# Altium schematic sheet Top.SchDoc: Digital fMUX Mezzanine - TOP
size 817 x 513 mm; Engineer: M.Dobbs, McGill U.; Revision: 4; PageSetup: Record=PageOptions|CenterHorizontal=True|CenterVertical=True|PrintScale=0.52|XCorrection=1.00|YCorrection=1.00|PrintKind=0|BorderSize=5000000|LeftOffset=0|BottomOffset=0|Orientation=2|PaperLength=1000|PaperWidth=1000|Scale=100|PaperSource=15|PrintQuality=1200|MediaType=1|DitherType=10|PaperKind=11 x 17|PrintScaleMode=1
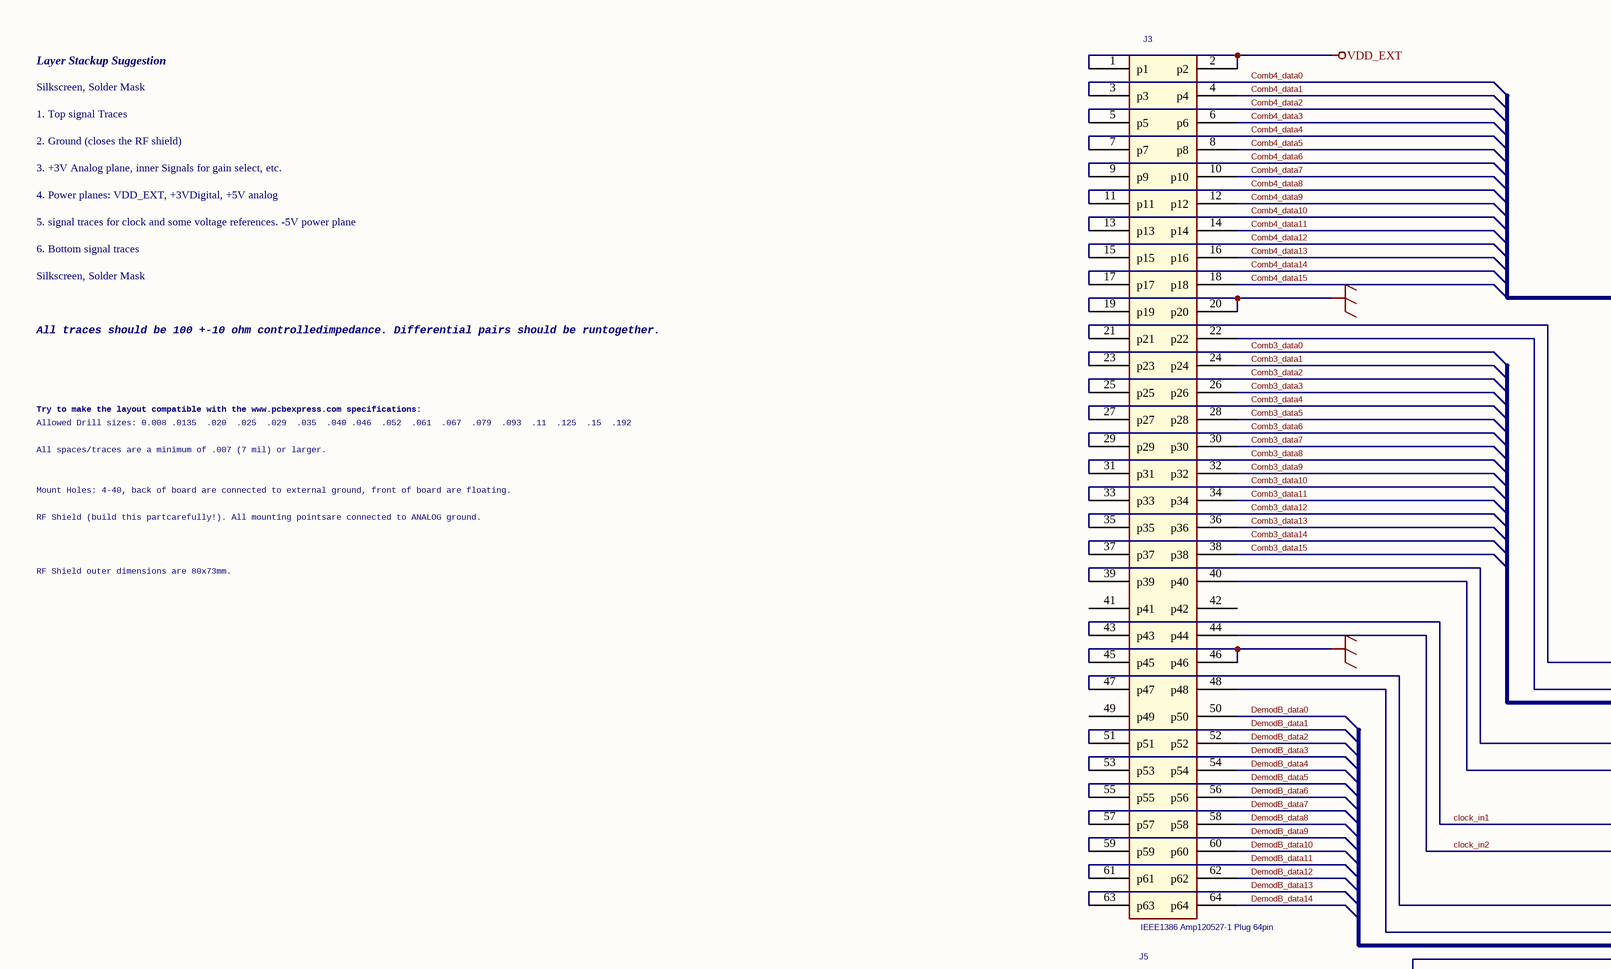
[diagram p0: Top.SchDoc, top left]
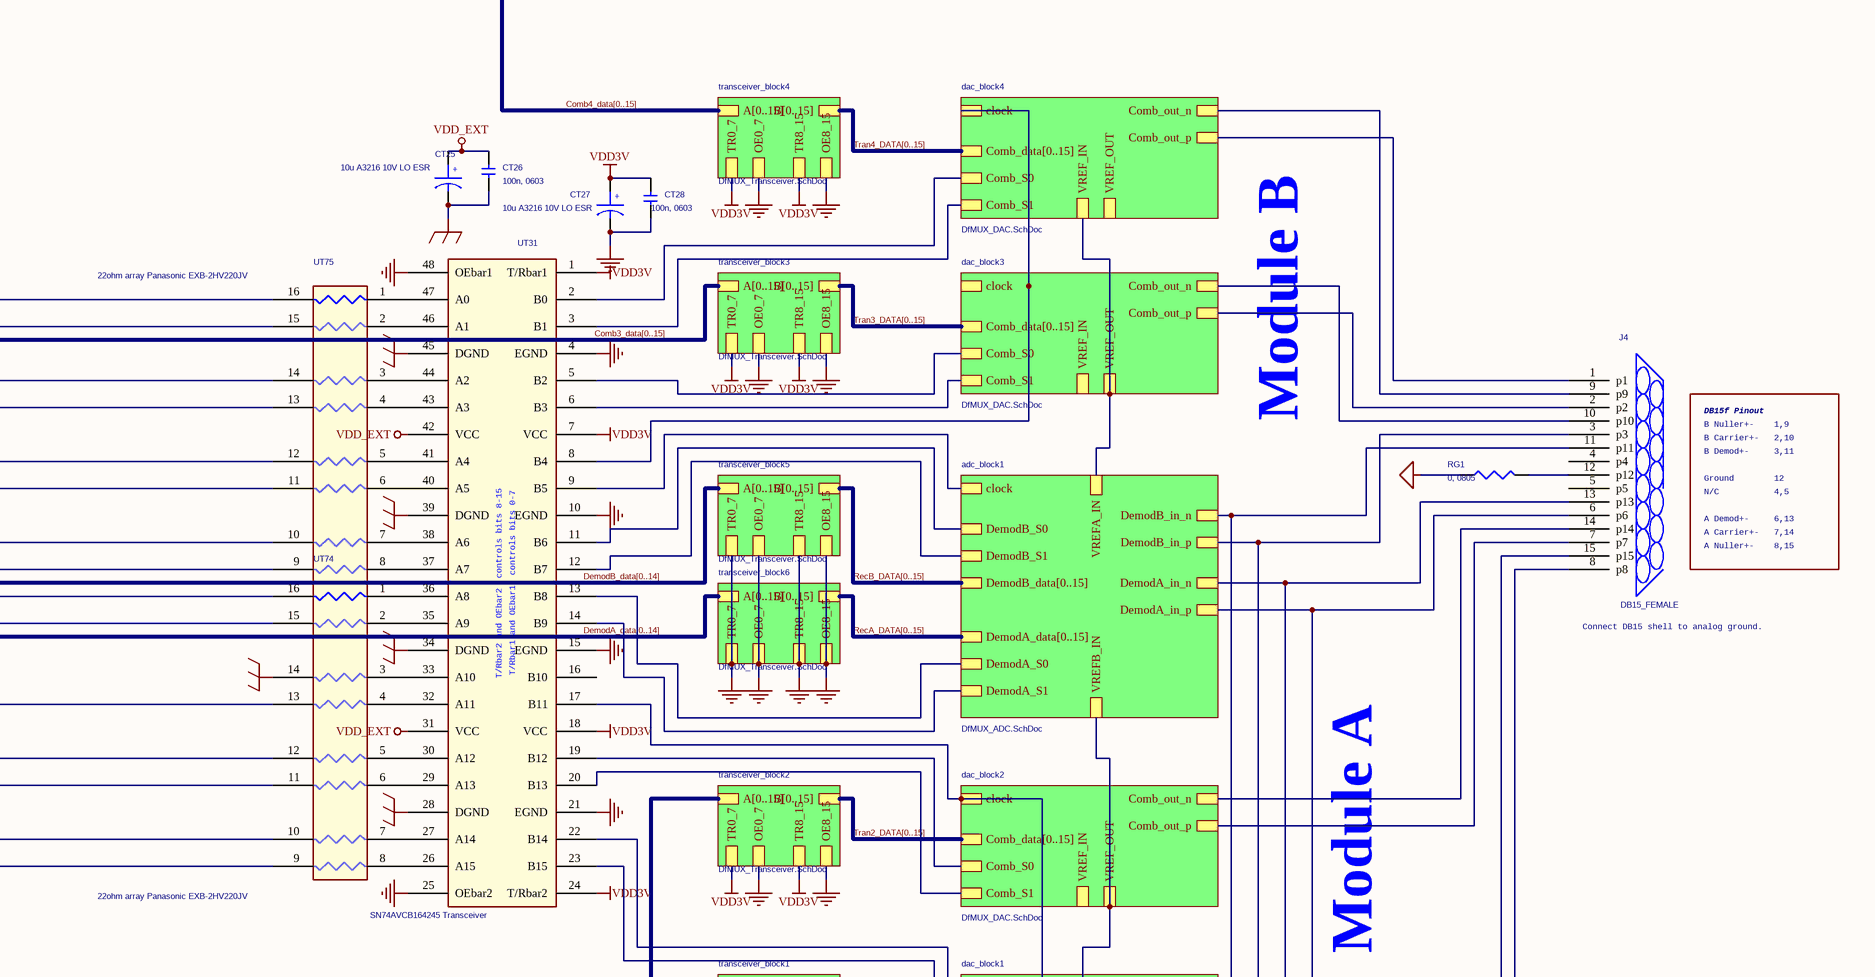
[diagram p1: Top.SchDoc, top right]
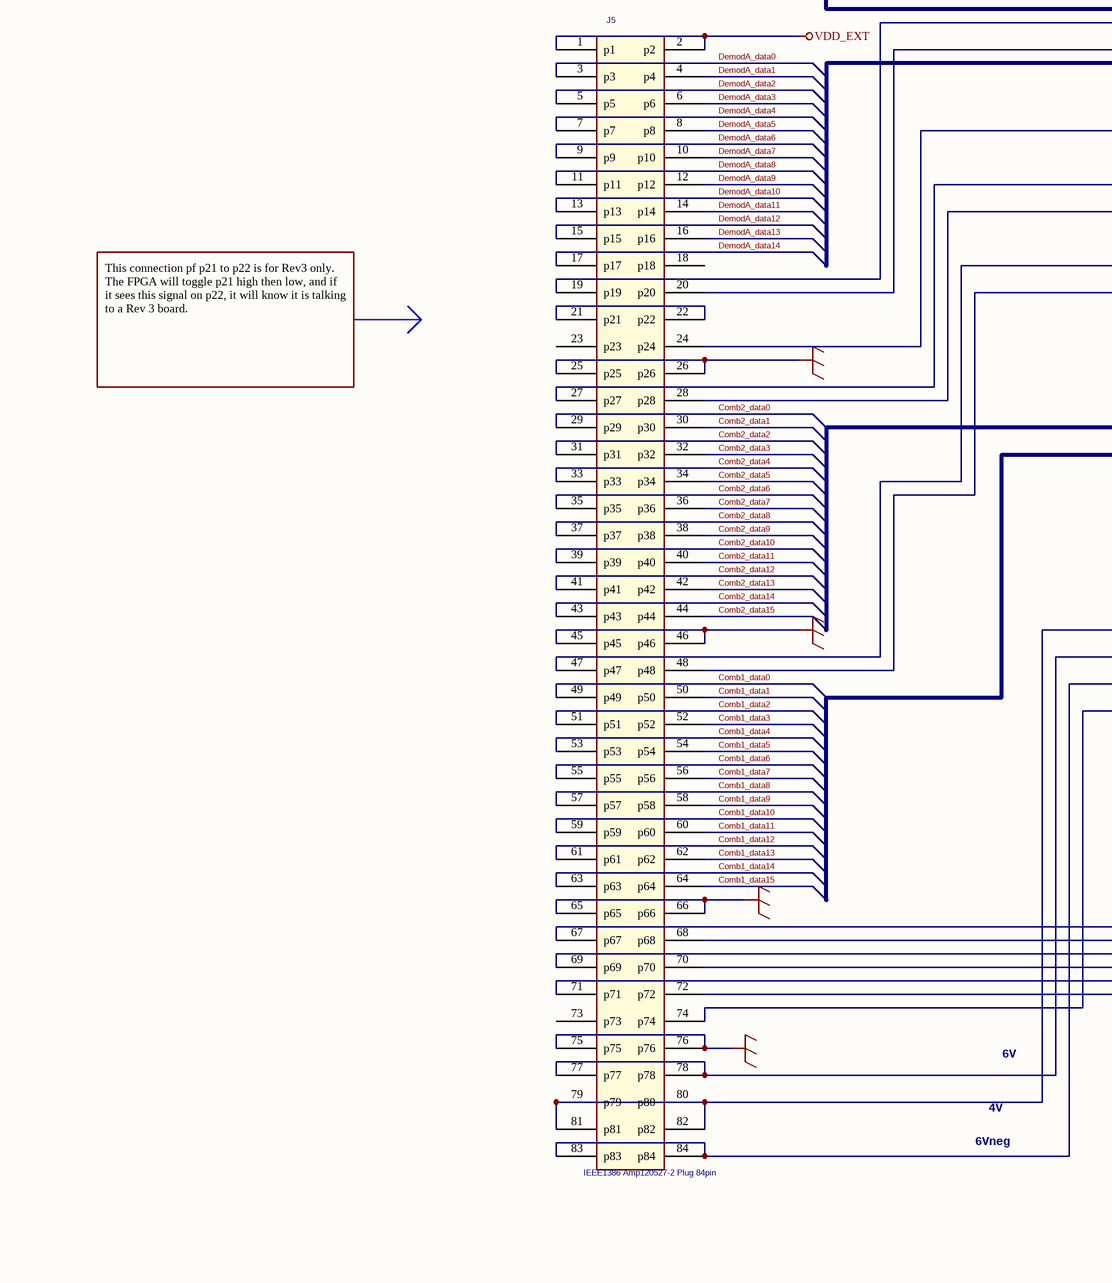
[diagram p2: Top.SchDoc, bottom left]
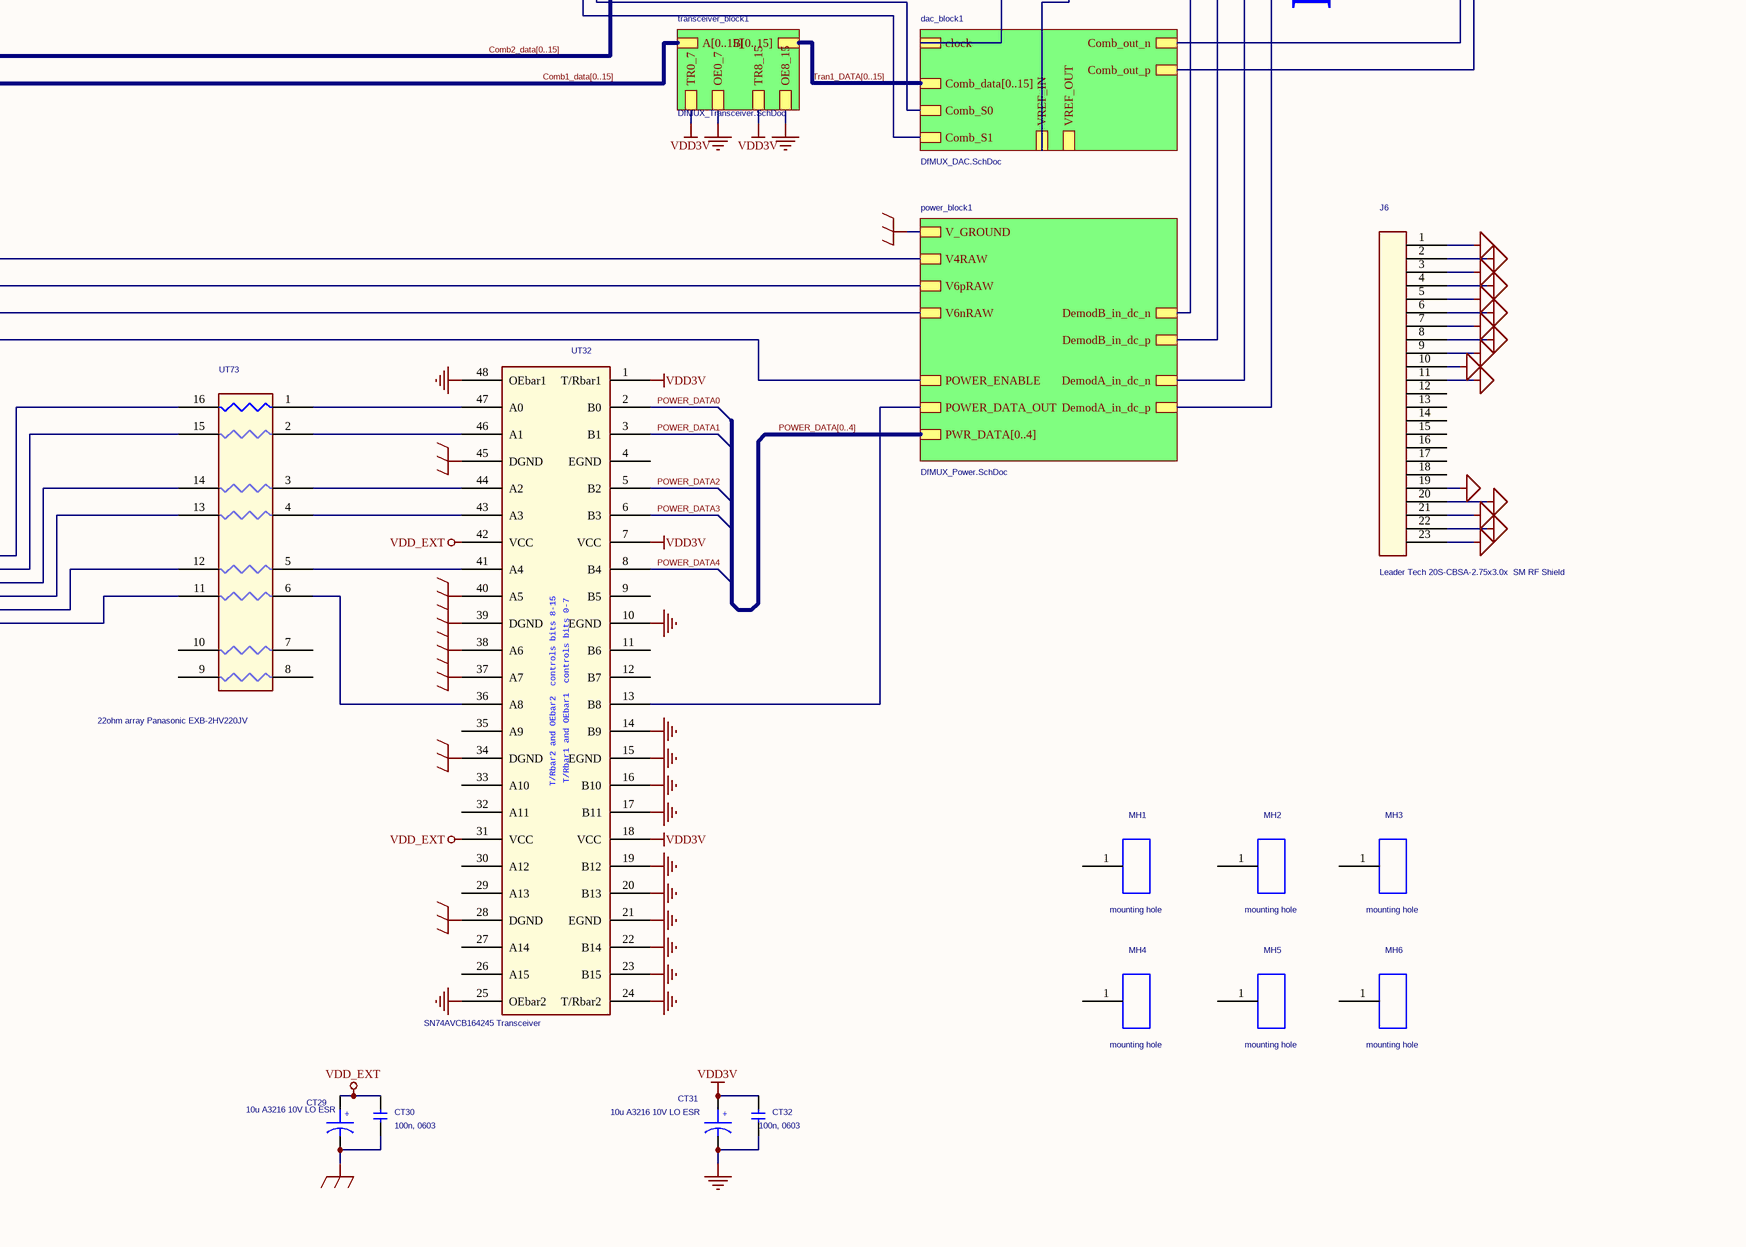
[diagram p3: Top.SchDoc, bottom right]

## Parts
CT25  10u A3216 10V LO ESR  [TANTA]
CT26  100n, 0603  [CK05]
CT27  10u A3216 10V LO ESR  [TANTA]
CT28  100n, 0603  [CK05]
CT29  10u A3216 10V LO ESR  [TANTA]
CT30  100n, 0603  [CK05]
CT31  10u A3216 10V LO ESR  [TANTA]
CT32  100n, 0603  [CK05]
J3  IEEE1386 Amp120527-1 Plug 64pin  [CON_AMP_1MM_64PINS]
J4  DB15_FEMALE  [DSUB/RS.318/TM/15]
J5  IEEE1386 Amp120527-2 Plug 84pin  [CON_AMP_1MM_84PINS]
J6  Leader Tech 20S-CBSA-2.75x3.0x  SM RF Shield  [SHIELD 2.75X3.00]
MH1  mounting hole  [MTHOLE.125]
MH2  mounting hole  [MTHOLE.125]
MH3  mounting hole  [MTHOLE.125]
MH4  mounting hole  [MTHOLE.125]
MH5  mounting hole  [MTHOLE.125]
MH6  mounting hole  [MTHOLE.125]
RG1  0, 0805
UT31  SN74AVCB164245 Transceiver  [TSSOP48]
UT32  SN74AVCB164245 Transceiver  [TSSOP48]
UT73  22ohm array Panasonic EXB-2HV220JV  [RN8.150X63]
UT74  22ohm array Panasonic EXB-2HV220JV  [RN8.150X63]
UT75  22ohm array Panasonic EXB-2HV220JV  [RN8.150X63]

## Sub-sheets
adc_block1 = DfMUX_ADC.SchDoc: DemodB_data[0..15], DemodA_data[0..15], clock, DemodA_S0, DemodA_S1, DemodB_S0, DemodB_S1, DemodB_in_p, DemodB_in_n, DemodA_in_n, DemodA_in_p, VREFA_IN, VREFB_IN
dac_block1 = DfMUX_DAC.SchDoc: Comb_data[0..15], Comb_S0, Comb_S1, Comb_out_p, Comb_out_n, clock, VREF_IN, VREF_OUT  | ReuseAnnotated: YES; Rd15_PartReference: RD17; Rd15_COMPLOC: [3002.633,445.433]; Rd30_PartReference: RD8; Rd30_COMPLOC: [3457.633,605.433]; Rd2set_PartReference: RD2SET1; Rd2set_COMPLOC: [2044.633,425.000]; Rd33_PartReference: RD15; Rd33_COMPLOC: [3002.633,500.433]; Cd9_PartReference: CD13; Cd9_COMPLOC: [2447.633,620.433]; Ld11_PartReference: LD1; Ld11_COMPLOC: [2202.633,700.433]; CD__PartReference: CD83; CD__COMPLOC: [3617.633,705.433]; Cd3_PartReference: CD9; Cd3_COMPLOC: [2087.633,640.433]; Rd36_PartReference: RD28; Rd36_COMPLOC: [2154.633,360.000]; Rd18_PartReference: RD4; Rd18_COMPLOC: [2947.633,610.433]; Rd38_PartReference: RD30; Rd38_COMPLOC: [2269.633,350.000]; Ud4_PartReference: UD3; Ud4_COMPLOC: [3517.633,435.433]; Rd29_PartReference: RD25; Rd29_COMPLOC: [3455.633,442.433]; Ud1_PartReference: UD1; Ud1_COMPLOC: [1689.033,701.833]; Ud3_PartReference: UD2; Ud3_COMPLOC: [3172.633,410.433]; Rd26_PartReference: RD7; Rd26_COMPLOC: [3102.633,555.433]; Cd14_PartReference: CD19; Cd14_COMPLOC: [2852.633,415.433]; Rd11_PartReference: RD16; Rd11_COMPLOC: [2392.633,565.433]; Cd10_PartReference: CD11; Cd10_COMPLOC: [2507.633,620.433]; Rd20_PartReference: RD2; Rd20_COMPLOC: [2947.633,665.433]; Jd1_PartReference: JD1; Jd1_COMPLOC: [2127.633,495.433]; Cd2_PartReference: CD8; Cd2_COMPLOC: [2032.633,640.433]; Rd13_PartReference: RD9; Rd13_COMPLOC: [2612.633,600.433]; Cd18_PartReference: CD5; Cd18_COMPLOC: [3402.633,605.433]; Rd24_PartReference: RD5; Rd24_COMPLOC: [3102.633,665.433]; Rd19_PartReference: RD22; Rd19_COMPLOC: [2947.633,390.433]; Cd8_PartReference: CD10; Cd8_COMPLOC: [2279.633,533.433]; Cd6_PartReference: CD3; Cd6_COMPLOC: [1877.633,700.433]; Cd__3_PartReference: CD92; Cd__3_COMPLOC: [3617.633,430.433]; Rd22_PartReference: RD21; Rd22_COMPLOC: [3047.633,445.433]; Rd34_PartReference: RD1; Rd34_COMPLOC: [3342.633,720.433]; Cd16_PartReference: CD1; Cd16_COMPLOC: [2732.633,700.433]; Rd35_PartReference: RD29; Rd35_COMPLOC: [3294.633,350.000]; Cd7_PartReference: CD4; Cd7_COMPLOC: [1797.633,635.367]; Cd4_PartReference: CD14; Cd4_COMPLOC: [1747.633,460.433]; Rd14_PartReference: RD19; Rd14_COMPLOC: [2612.633,505.433]; Rd32_PartReference: RD13; Rd32_COMPLOC: [3722.633,600.000]; Cd15_PartReference: CD2; Cd15_COMPLOC: [2532.633,700.433]; Rd31_PartReference: RD18; Rd31_COMPROT: 0; Rd31_COMPLOC: [3722.633,534.367]; Ld14_PartReference: LD4; Ld14_COMPLOC: [2467.633,505.433]; Rd21_PartReference: RD23; Rd21_COMPLOC: [3047.633,390.433]; Rd37_PartReference: RD20; Rd37_COMPLOC: [2151.633,417.000]; Ld12_PartReference: LD3; Ld12_COMPLOC: [2337.633,425.433]; Rd12_PartReference: RD14; Rd12_COMPLOC: [2567.633,620.433]; Rd33_1_PartReference: RD11; Rd33_1_COMPLOC: [2392.633,620.433]; Rd28_PartReference: RD3; Rd28_COMPLOC: [3402.633,660.433]; Rd27_PartReference: RD27; Rd27_COMPLOC: [3397.633,390.433]; Rd23_PartReference: RD24; Rd23_COMPLOC: [3046.633,500.433]; Ld13_PartReference: LD2; Ld13_COMPLOC: [2372.633,700.433]; Cd19_PartReference: CD6; Cd19_COMPLOC: [3159.633,720.000]; CD__1_PartReference: CD84; CD__1_COMPLOC: [3657.633,360.433]; Cd1_PartReference: CD17; Cd1_COMPLOC: [2057.633,378.000]; Rd16_PartReference: RD26; Rd16_COMPLOC: [2732.633,355.433]; Rd25_PartReference: RD6; Rd25_COMPLOC: [3102.633,610.433]; Rd17_PartReference: RD12; Rd17_COMPLOC: [2947.633,555.433]; Cd5_PartReference: CD15; Cd5_COMPLOC: [1892.633,530.433]; Cd13_PartReference: CD20; Cd13_COMPLOC: [2847.633,355.433]; Rd10_PartReference: RD10; Rd10_COMPLOC: [2337.633,510.433]; Ud2_PartReference: UD4; Ud2_COMPLOC: [2877.633,625.433]; Cd__2_PartReference: CD91; Cd__2_COMPLOC: [3454.633,650.000]; Cd17_PartReference: CD18; Cd17_COMPLOC: [3397.633,440.433]; TitleBlock_2_Page_Number: 4
dac_block2 = DfMUX_DAC.SchDoc: Comb_data[0..15], Comb_S0, Comb_S1, Comb_out_p, Comb_out_n, clock, VREF_IN, VREF_OUT  | ReuseAnnotated: YES; Rd15_PartReference: RD47; Rd15_COMPLOC: [3002.633,891.433]; Rd30_PartReference: RD38; Rd30_COMPLOC: [3457.633,1051.433]; Rd2set_PartReference: RD2SET2; Rd2set_COMPLOC: [2055.633,875.000]; Rd33_PartReference: RD45; Rd33_COMPLOC: [3002.633,946.433]; Cd9_PartReference: CD33; Cd9_COMPLOC: [2447.633,1066.433]; Ld11_PartReference: LD5; Ld11_COMPLOC: [2224.633,1140.000]; CD__PartReference: CD85; CD__COMPLOC: [3617.633,1151.433]; Cd3_PartReference: CD29; Cd3_COMPLOC: [2087.633,1086.433]; Rd36_PartReference: RD58; Rd36_COMPLOC: [2157.633,820.000]; Rd18_PartReference: RD34; Rd18_COMPLOC: [2947.633,1056.433]; Rd38_PartReference: RD60; Rd38_COMPLOC: [2292.633,806.433]; Ud4_PartReference: UD7; Ud4_COMPLOC: [3517.633,881.433]; Rd29_PartReference: RD55; Rd29_COMPLOC: [3455.633,888.433]; Ud1_PartReference: UD5; Ud1_COMPLOC: [1689.033,1147.833]; Ud3_PartReference: UD6; Ud3_COMPLOC: [3172.633,856.433]; Rd26_PartReference: RD37; Rd26_COMPLOC: [3102.633,1001.433]; Cd14_PartReference: CD39; Cd14_COMPLOC: [2852.633,861.433]; Rd11_PartReference: RD46; Rd11_COMPLOC: [2392.633,1011.433]; Cd10_PartReference: CD31; Cd10_COMPLOC: [2507.633,1066.433]; Rd20_PartReference: RD32; Rd20_COMPLOC: [2947.633,1111.433]; Jd1_PartReference: JD2; Jd1_COMPLOC: [2127.633,941.433]; Cd2_PartReference: CD28; Cd2_COMPLOC: [2032.633,1086.433]; Rd13_PartReference: RD39; Rd13_COMPLOC: [2612.633,1046.433]; Cd18_PartReference: CD25; Cd18_COMPLOC: [3402.633,1051.433]; Rd24_PartReference: RD35; Rd24_COMPLOC: [3102.633,1111.433]; Rd19_PartReference: RD52; Rd19_COMPLOC: [2947.633,836.433]; Cd8_PartReference: CD30; Cd8_COMPLOC: [2279.633,979.433]; Cd6_PartReference: CD23; Cd6_COMPLOC: [1877.633,1146.433]; Cd__3_PartReference: CD94; Cd__3_COMPLOC: [3617.633,876.433]; Rd22_PartReference: RD51; Rd22_COMPLOC: [3047.633,891.433]; Rd34_PartReference: RD31; Rd34_COMPLOC: [3342.633,1166.433]; Cd16_PartReference: CD21; Cd16_COMPLOC: [2732.633,1146.433]; Rd35_PartReference: RD59; Rd35_COMPLOC: [3292.633,796.433]; Cd7_PartReference: CD24; Cd7_COMPLOC: [1799.633,1080.000]; Cd4_PartReference: CD34; Cd4_COMPLOC: [1747.633,906.433]; Rd14_PartReference: RD49; Rd14_COMPLOC: [2612.633,951.433]; Rd32_PartReference: RD43; Rd32_COMPLOC: [3719.633,1036.367]; Cd15_PartReference: CD22; Cd15_COMPLOC: [2532.633,1146.433]; Rd31_PartReference: RD48; Rd31_COMPROT: 0; Rd31_COMPLOC: [3719.633,982.367]; Ld14_PartReference: LD8; Ld14_COMPLOC: [2467.633,951.433]; Rd21_PartReference: RD53; Rd21_COMPLOC: [3047.633,836.433]; Rd37_PartReference: RD50; Rd37_COMPLOC: [2158.633,875.000]; Ld12_PartReference: LD7; Ld12_COMPLOC: [2337.633,871.433]; Rd12_PartReference: RD44; Rd12_COMPLOC: [2567.633,1066.433]; Rd33_1_PartReference: RD41; Rd33_1_COMPLOC: [2392.633,1066.433]; Rd28_PartReference: RD33; Rd28_COMPLOC: [3402.633,1106.433]; Rd27_PartReference: RD57; Rd27_COMPLOC: [3397.633,836.433]; Rd23_PartReference: RD54; Rd23_COMPLOC: [3046.633,946.433]; Ld13_PartReference: LD6; Ld13_COMPLOC: [2369.633,1140.000]; Cd19_PartReference: CD26; Cd19_COMPLOC: [3159.633,1165.000]; CD__1_PartReference: CD86; CD__1_COMPLOC: [3657.633,806.433]; Cd1_PartReference: CD37; Cd1_COMPLOC: [2054.633,820.000]; Rd16_PartReference: RD56; Rd16_COMPLOC: [2732.633,801.433]; Rd25_PartReference: RD36; Rd25_COMPLOC: [3102.633,1056.433]; Rd17_PartReference: RD42; Rd17_COMPLOC: [2947.633,1001.433]; Cd5_PartReference: CD35; Cd5_COMPLOC: [1892.633,976.433]; Cd13_PartReference: CD40; Cd13_COMPLOC: [2847.633,801.433]; Rd10_PartReference: RD40; Rd10_COMPLOC: [2337.633,956.433]; Ud2_PartReference: UD8; Ud2_COMPLOC: [2874.633,1070.000]; Cd__2_PartReference: CD93; Cd__2_COMPLOC: [3454.633,1095.000]; Cd17_PartReference: CD38; Cd17_COMPLOC: [3397.633,886.433]; TitleBlock_2_Page_Number: 5
dac_block3 = DfMUX_DAC.SchDoc: Comb_data[0..15], Comb_S0, Comb_S1, Comb_out_p, Comb_out_n, clock, VREF_IN, VREF_OUT  | ReuseAnnotated: YES; Rd15_PartReference: RD77; Rd15_COMPLOC: [3007.633,2511.433]; Rd30_PartReference: RD68; Rd30_COMPLOC: [3462.633,2671.433]; Rd2set_PartReference: RD2SET3; Rd2set_COMPLOC: [2054.633,2493.000]; Rd33_PartReference: RD75; Rd33_COMPLOC: [3007.633,2566.433]; Cd9_PartReference: CD53; Cd9_COMPLOC: [2452.633,2686.433]; Ld11_PartReference: LD9; Ld11_COMPLOC: [2207.633,2766.433]; CD__PartReference: CD87; CD__COMPLOC: [3622.633,2771.433]; Cd3_PartReference: CD49; Cd3_COMPLOC: [2092.633,2706.433]; Rd36_PartReference: RD88; Rd36_COMPLOC: [2157.633,2434.000]; Rd18_PartReference: RD64; Rd18_COMPLOC: [2952.633,2676.433]; Rd38_PartReference: RD90; Rd38_COMPLOC: [2297.633,2426.433]; Ud4_PartReference: UD11; Ud4_COMPLOC: [3522.633,2501.433]; Rd29_PartReference: RD85; Rd29_COMPLOC: [3460.633,2508.433]; Ud1_PartReference: UD9; Ud1_COMPLOC: [1694.033,2767.833]; Ud3_PartReference: UD10; Ud3_COMPLOC: [3177.633,2476.433]; Rd26_PartReference: RD67; Rd26_COMPLOC: [3107.633,2621.433]; Cd14_PartReference: CD59; Cd14_COMPLOC: [2857.633,2481.433]; Rd11_PartReference: RD76; Rd11_COMPLOC: [2397.633,2631.433]; Cd10_PartReference: CD51; Cd10_COMPLOC: [2512.633,2686.433]; Rd20_PartReference: RD62; Rd20_COMPLOC: [2952.633,2731.433]; Jd1_PartReference: JD3; Jd1_COMPLOC: [2132.633,2561.433]; Cd2_PartReference: CD48; Cd2_COMPLOC: [2037.633,2706.433]; Rd13_PartReference: RD69; Rd13_COMPLOC: [2617.633,2666.433]; Cd18_PartReference: CD45; Cd18_COMPLOC: [3407.633,2671.433]; Rd24_PartReference: RD65; Rd24_COMPLOC: [3107.633,2731.433]; Rd19_PartReference: RD82; Rd19_COMPLOC: [2952.633,2456.433]; Cd8_PartReference: CD50; Cd8_COMPLOC: [2284.633,2599.433]; Cd6_PartReference: CD43; Cd6_COMPLOC: [1882.633,2766.433]; Cd__3_PartReference: CD96; Cd__3_COMPLOC: [3622.633,2496.433]; Rd22_PartReference: RD81; Rd22_COMPLOC: [3052.633,2511.433]; Rd34_PartReference: RD61; Rd34_COMPLOC: [3347.633,2786.433]; Cd16_PartReference: CD41; Cd16_COMPLOC: [2737.633,2766.433]; Rd35_PartReference: RD89; Rd35_COMPLOC: [3294.633,2415.000]; Cd7_PartReference: CD44; Cd7_COMPLOC: [1804.633,2700.000]; Cd4_PartReference: CD54; Cd4_COMPLOC: [1752.633,2526.433]; Rd14_PartReference: RD79; Rd14_COMPLOC: [2617.633,2571.433]; Rd32_PartReference: RD73; Rd32_COMPLOC: [3725.633,2662.000]; Cd15_PartReference: CD42; Cd15_COMPLOC: [2537.633,2766.433]; Rd31_PartReference: RD78; Rd31_COMPROT: 90; Rd31_COMPLOC: [3727.633,2471.433]; Ld14_PartReference: LD12; Ld14_COMPLOC: [2472.633,2571.433]; Rd21_PartReference: RD83; Rd21_COMPLOC: [3052.633,2456.433]; Rd37_PartReference: RD80; Rd37_COMPLOC: [2157.633,2493.000]; Ld12_PartReference: LD11; Ld12_COMPLOC: [2342.633,2491.433]; Rd12_PartReference: RD74; Rd12_COMPLOC: [2572.633,2686.433]; Rd33_1_PartReference: RD71; Rd33_1_COMPLOC: [2397.633,2686.433]; Rd28_PartReference: RD63; Rd28_COMPLOC: [3407.633,2726.433]; Rd27_PartReference: RD87; Rd27_COMPLOC: [3402.633,2456.433]; Rd23_PartReference: RD84; Rd23_COMPLOC: [3051.633,2566.433]; Ld13_PartReference: LD10; Ld13_COMPLOC: [2377.633,2766.433]; Cd19_PartReference: CD46; Cd19_COMPLOC: [3164.633,2785.000]; CD__1_PartReference: CD88; CD__1_COMPLOC: [3662.633,2426.433]; Cd1_PartReference: CD57; Cd1_COMPLOC: [2054.633,2435.000]; Rd16_PartReference: RD86; Rd16_COMPLOC: [2737.633,2421.433]; Rd25_PartReference: RD66; Rd25_COMPLOC: [3107.633,2676.433]; Rd17_PartReference: RD72; Rd17_COMPLOC: [2952.633,2621.433]; Cd5_PartReference: CD55; Cd5_COMPLOC: [1897.633,2596.433]; Cd13_PartReference: CD60; Cd13_COMPLOC: [2852.633,2421.433]; Rd10_PartReference: RD70; Rd10_COMPLOC: [2342.633,2576.433]; Ud2_PartReference: UD12; Ud2_COMPLOC: [2879.633,2690.000]; Cd__2_PartReference: CD95; Cd__2_COMPLOC: [3459.633,2715.000]; Cd17_PartReference: CD58; Cd17_COMPLOC: [3402.633,2506.433]; TitleBlock_2_Page_Number: 6
dac_block4 = DfMUX_DAC.SchDoc: Comb_data[0..15], Comb_S0, Comb_S1, Comb_out_p, Comb_out_n, clock, VREF_IN, VREF_OUT  | ReuseAnnotated: YES; Rd15_PartReference: RD107; Rd15_COMPLOC: [3012.633,2966.433]; Rd30_PartReference: RD98; Rd30_COMPLOC: [3467.633,3126.433]; Rd2set_PartReference: RD2SET4; Rd2set_COMPLOC: [2055.633,2956.000]; Rd33_PartReference: RD105; Rd33_COMPLOC: [3012.633,3021.433]; Cd9_PartReference: CD73; Cd9_COMPLOC: [2457.633,3141.433]; Ld11_PartReference: LD13; Ld11_COMPLOC: [2212.633,3221.433]; CD__PartReference: CD89; CD__COMPLOC: [3627.633,3226.433]; Cd3_PartReference: CD69; Cd3_COMPLOC: [2097.633,3161.433]; Rd36_PartReference: RD118; Rd36_COMPLOC: [2161.633,2901.000]; Rd18_PartReference: RD94; Rd18_COMPLOC: [2957.633,3131.433]; Rd38_PartReference: RD120; Rd38_COMPLOC: [2302.633,2881.433]; Ud4_PartReference: UD15; Ud4_COMPLOC: [3527.633,2956.433]; Rd29_PartReference: RD115; Rd29_COMPLOC: [3465.633,2963.433]; Ud1_PartReference: UD13; Ud1_COMPLOC: [1699.033,3222.833]; Ud3_PartReference: UD14; Ud3_COMPLOC: [3182.633,2931.433]; Rd26_PartReference: RD97; Rd26_COMPLOC: [3112.633,3076.433]; Cd14_PartReference: CD79; Cd14_COMPLOC: [2862.633,2936.433]; Rd11_PartReference: RD106; Rd11_COMPLOC: [2402.633,3086.433]; Cd10_PartReference: CD71; Cd10_COMPLOC: [2517.633,3141.433]; Rd20_PartReference: RD92; Rd20_COMPLOC: [2957.633,3186.433]; Jd1_PartReference: JD4; Jd1_COMPLOC: [2137.633,3016.433]; Cd2_PartReference: CD68; Cd2_COMPLOC: [2042.633,3161.433]; Rd13_PartReference: RD99; Rd13_COMPLOC: [2622.633,3121.433]; Cd18_PartReference: CD65; Cd18_COMPLOC: [3412.633,3126.433]; Rd24_PartReference: RD95; Rd24_COMPLOC: [3112.633,3186.433]; Rd19_PartReference: RD112; Rd19_COMPLOC: [2957.633,2911.433]; Cd8_PartReference: CD70; Cd8_COMPLOC: [2289.633,3054.433]; Cd6_PartReference: CD63; Cd6_COMPLOC: [1887.633,3221.433]; Cd__3_PartReference: CD98; Cd__3_COMPLOC: [3627.633,2951.433]; Rd22_PartReference: RD111; Rd22_COMPLOC: [3057.633,2966.433]; Rd34_PartReference: RD91; Rd34_COMPLOC: [3352.633,3241.433]; Cd16_PartReference: CD61; Cd16_COMPLOC: [2742.633,3221.433]; Rd35_PartReference: RD119; Rd35_COMPLOC: [3302.633,2871.433]; Cd7_PartReference: CD64; Cd7_COMPLOC: [1807.633,3156.367]; Cd4_PartReference: CD74; Cd4_COMPLOC: [1754.633,2985.000]; Rd14_PartReference: RD109; Rd14_COMPLOC: [2622.633,3026.433]; Rd32_PartReference: RD103; Rd32_COMPLOC: [3733.633,3106.000]; Cd15_PartReference: CD62; Cd15_COMPLOC: [2542.633,3221.433]; Rd31_PartReference: RD108; Rd31_COMPROT: 90; Rd31_COMPLOC: [3732.633,2926.433]; Ld14_PartReference: LD16; Ld14_COMPLOC: [2477.633,3026.433]; Rd21_PartReference: RD113; Rd21_COMPLOC: [3057.633,2911.433]; Rd37_PartReference: RD110; Rd37_COMPLOC: [2161.633,2956.000]; Ld12_PartReference: LD15; Ld12_COMPLOC: [2347.633,2946.433]; Rd12_PartReference: RD104; Rd12_COMPLOC: [2577.633,3141.433]; Rd33_1_PartReference: RD101; Rd33_1_COMPLOC: [2402.633,3141.433]; Rd28_PartReference: RD93; Rd28_COMPLOC: [3412.633,3181.433]; Rd27_PartReference: RD117; Rd27_COMPLOC: [3407.633,2911.433]; Rd23_PartReference: RD114; Rd23_COMPLOC: [3056.633,3021.433]; Ld13_PartReference: LD14; Ld13_COMPLOC: [2382.633,3221.433]; Cd19_PartReference: CD66; Cd19_COMPLOC: [3169.633,3240.000]; CD__1_PartReference: CD90; CD__1_COMPLOC: [3667.633,2881.433]; Cd1_PartReference: CD77; Cd1_COMPLOC: [2057.633,2901.000]; Rd16_PartReference: RD116; Rd16_COMPLOC: [2742.633,2876.433]; Rd25_PartReference: RD96; Rd25_COMPLOC: [3112.633,3131.433]; Rd17_PartReference: RD102; Rd17_COMPLOC: [2957.633,3076.433]; Cd5_PartReference: CD75; Cd5_COMPLOC: [1902.633,3051.433]; Cd13_PartReference: CD80; Cd13_COMPLOC: [2857.633,2876.433]; Rd10_PartReference: RD100; Rd10_COMPLOC: [2347.633,3031.433]; Ud2_PartReference: UD16; Ud2_COMPLOC: [2884.633,3145.000]; Cd__2_PartReference: CD97; Cd__2_COMPLOC: [3459.633,3170.000]; Cd17_PartReference: CD78; Cd17_COMPLOC: [3407.633,2961.433]; TitleBlock_2_Page_Number: 7
power_block1 = DfMUX_Power.SchDoc: V4RAW, V6pRAW, V6nRAW, V_GROUND, POWER_ENABLE, PWR_DATA[0..4], DemodA_in_dc_p, DemodB_in_dc_p, POWER_DATA_OUT, DemodB_in_dc_n, DemodA_in_dc_n
transceiver_block1 = DfMUX_Transceiver.SchDoc: B[0..15], A[0..15], TR0_7, TR8_15, OE0_7, OE8_15  | Ct3_PartReference: CT37; Ct3_COMPLOC: [1187.633,883.367]; t4_PartReference: CT38; t4_COMPLOC: [1174.633,637.367]; Ct1_PartReference: CT39; Ct1_COMPLOC: [968.633,893.367]; Ct2_PartReference: CT40; Ct2_COMPLOC: [933.633,691.367]; UT__1_PartReference: UT62; UT__1_COMPLOC: [784.633,679.367]; Ut1_PartReference: UT40; Ut1_COMPLOC: [1187.633,958.367]; UT__PartReference: UT61; UT__COMPLOC: [784.633,874.367]; TitleBlock_Page_Number: 9
transceiver_block2 = DfMUX_Transceiver.SchDoc: B[0..15], A[0..15], TR0_7, TR8_15, OE0_7, OE8_15  | Ct3_PartReference: CT49; Ct3_COMPLOC: [1189.633,1295.367]; t4_PartReference: CT50; t4_COMPLOC: [1176.633,1049.367]; Ct1_PartReference: CT51; Ct1_COMPLOC: [970.633,1305.367]; Ct2_PartReference: CT52; Ct2_COMPLOC: [935.633,1103.367]; UT__1_PartReference: UT64; UT__1_COMPLOC: [779.633,1089.367]; Ut1_PartReference: UT55; Ut1_COMPLOC: [1189.633,1370.367]; UT__PartReference: UT63; UT__COMPLOC: [779.633,1284.367]; TitleBlock_Page_Number: 10
transceiver_block3 = DfMUX_Transceiver.SchDoc: B[0..15], A[0..15], TR0_7, TR8_15, OE0_7, OE8_15  | Ct3_PartReference: CT41; Ct3_COMPLOC: [1189.633,2936.367]; t4_PartReference: CT42; t4_COMPLOC: [1176.633,2690.367]; Ct1_PartReference: CT43; Ct1_COMPLOC: [970.633,2946.367]; Ct2_PartReference: CT44; Ct2_COMPLOC: [935.633,2744.367]; UT__1_PartReference: UT66; UT__1_COMPLOC: [779.633,2734.367]; Ut1_PartReference: UT45; Ut1_COMPLOC: [1189.633,3011.367]; UT__PartReference: UT65; UT__COMPLOC: [779.633,2926.367]; TitleBlock_Page_Number: 11
transceiver_block4 = DfMUX_Transceiver.SchDoc: B[0..15], A[0..15], TR0_7, TR8_15, OE0_7, OE8_15  | Ct3_PartReference: CT53; Ct3_COMPLOC: [1188.633,3349.367]; t4_PartReference: CT54; t4_COMPLOC: [1175.633,3103.367]; Ct1_PartReference: CT55; Ct1_COMPLOC: [969.633,3359.367]; Ct2_PartReference: CT56; Ct2_COMPLOC: [934.633,3157.367]; UT__1_PartReference: UT68; UT__1_COMPLOC: [779.633,3144.367]; Ut1_PartReference: UT60; Ut1_COMPLOC: [1188.633,3424.367]; UT__PartReference: UT67; UT__COMPLOC: [779.633,3339.367]; TitleBlock_Page_Number: 12
transceiver_block5 = DfMUX_Transceiver.SchDoc: B[0..15], A[0..15], TR0_7, TR8_15, OE0_7, OE8_15  | Ct3_PartReference: CT45; Ct3_COMPLOC: [1188.633,2114.367]; t4_PartReference: CT46; t4_COMPLOC: [1175.633,1868.367]; Ct1_PartReference: CT47; Ct1_COMPLOC: [969.633,2124.367]; Ct2_PartReference: CT48; Ct2_COMPLOC: [934.633,1922.367]; UT__1_PartReference: UT70; UT__1_COMPLOC: [779.633,1909.367]; Ut1_PartReference: UT50; Ut1_COMPLOC: [1188.633,2189.367]; UT__PartReference: UT69; UT__COMPLOC: [779.633,2104.367]; TitleBlock_Page_Number: 13
transceiver_block6 = DfMUX_Transceiver.SchDoc: B[0..15], A[0..15], TR0_7, TR8_15, OE0_7, OE8_15  | Ct3_PartReference: CT33; Ct3_COMPLOC: [1188.633,1705.367]; t4_PartReference: CT34; t4_COMPLOC: [1175.633,1459.367]; Ct1_PartReference: CT35; Ct1_COMPLOC: [969.633,1715.367]; Ct2_PartReference: CT36; Ct2_COMPLOC: [934.633,1513.367]; UT__1_PartReference: UT72; UT__1_COMPLOC: [779.633,1499.367]; Ut1_PartReference: UT35; Ut1_COMPLOC: [1188.633,1780.367]; UT__PartReference: UT71; UT__COMPLOC: [779.633,1694.367]; TitleBlock_Page_Number: 14

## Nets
GND_DIG: CT27.2 CT28.1 CT31.2 CT32.1 UT31.4(EGND) UT31.10(EGND) UT31.15(EGND) UT31.21(EGND) UT31.25(OEbar2) UT31.48(OEbar1) UT32.10(EGND) UT32.14(B9) UT32.15(EGND) UT32.16(B10) UT32.17(B11) UT32.19(B12) UT32.20(B13) UT32.21(EGND) UT32.22(B14) UT32.23(B15) UT32.24(T/Rbar2) UT32.25(OEbar2) UT32.48(OEbar1) ; sheet transceiver_block2/OE0_7, sheet transceiver_block2/OE8_15, sheet transceiver_block3/OE0_7, sheet transceiver_block3/OE8_15, sheet transceiver_block6/TR0_7, sheet transceiver_block6/TR8_15, sheet transceiver_block6/OE0_7, sheet transceiver_block6/OE8_15, sheet transceiver_block1/OE0_7, sheet transceiver_block1/OE8_15, sheet transceiver_block5/TR0_7, sheet transceiver_block5/TR8_15, sheet transceiver_block5/OE0_7, sheet transceiver_block5/OE8_15, sheet transceiver_block4/OE0_7, sheet transceiver_block4/OE8_15
GND_EARTH: CT25.2 CT26.1 CT29.2 CT30.1 J3.19(p19) J3.20(p20) J3.45(p45) J3.46(p46) J5.25(p25) J5.26(p26) J5.45(p45) J5.46(p46) J5.65(p65) J5.66(p66) J5.75(p75) J5.76(p76) UT31.28(DGND) UT31.34(DGND) UT31.39(DGND) UT31.45(DGND) UT32.28(DGND) UT32.34(DGND) UT32.37(A7) UT32.38(A6) UT32.39(DGND) UT32.40(A5) UT32.45(DGND) UT74.14(R3) ; sheet power_block1/V_GROUND
GND_SIGNAL: J6.1 J6.2 J6.3 J6.4 J6.5 J6.6 J6.7 J6.8 J6.9 J6.10 J6.11 J6.19 J6.20 J6.21 J6.22 J6.23 RG1.1
VDD3V: CT27.1 CT28.2 CT31.1 CT32.2 UT31.1(T/Rbar1) UT31.7(VCC) UT31.18(VCC) UT31.24(T/Rbar2) UT32.1(T/Rbar1) UT32.7(VCC) UT32.18(VCC) ; sheet transceiver_block2/TR0_7, sheet transceiver_block2/TR8_15, sheet transceiver_block3/TR0_7, sheet transceiver_block3/TR8_15, sheet transceiver_block1/TR0_7, sheet transceiver_block1/TR8_15, sheet transceiver_block4/TR0_7, sheet transceiver_block4/TR8_15
VDD_EXT: CT25.1 CT26.2 CT29.1 CT30.2 J3.1(p1) J3.2(p2) J5.1(p1) J5.2(p2) UT31.31(VCC) UT31.42(VCC) UT32.31(VCC) UT32.42(VCC)
clock_in1: J3.43(p43) UT75.12(R5)
clock_in2: J3.44(p44) UT75.11(R6)
Comb1_data0: J5.49(p49)
Comb1_data1: J5.50(p50)
Comb1_data2: J5.51(p51)
Comb1_data3: J5.52(p52)
Comb1_data4: J5.53(p53)
Comb1_data5: J5.54(p54)
Comb1_data6: J5.55(p55)
Comb1_data7: J5.56(p56)
Comb1_data8: J5.57(p57)
Comb1_data9: J5.58(p58)
Comb1_data10: J5.59(p59)
Comb1_data11: J5.60(p60)
Comb1_data12: J5.61(p61)
Comb1_data13: J5.62(p62)
Comb1_data14: J5.63(p63)
Comb1_data15: J5.64(p64)
Comb2_data0: J5.29(p29)
Comb2_data1: J5.30(p30)
Comb2_data2: J5.31(p31)
Comb2_data3: J5.32(p32)
Comb2_data4: J5.33(p33)
Comb2_data5: J5.34(p34)
Comb2_data6: J5.35(p35)
Comb2_data7: J5.36(p36)
Comb2_data8: J5.37(p37)
Comb2_data9: J5.38(p38)
Comb2_data10: J5.39(p39)
Comb2_data11: J5.40(p40)
Comb2_data12: J5.41(p41)
Comb2_data13: J5.42(p42)
Comb2_data14: J5.43(p43)
Comb2_data15: J5.44(p44)
Comb3_data0: J3.23(p23)
Comb3_data1: J3.24(p24)
Comb3_data2: J3.25(p25)
Comb3_data3: J3.26(p26)
Comb3_data4: J3.27(p27)
Comb3_data5: J3.28(p28)
Comb3_data6: J3.29(p29)
Comb3_data7: J3.30(p30)
Comb3_data8: J3.31(p31)
Comb3_data9: J3.32(p32)
Comb3_data10: J3.33(p33)
Comb3_data11: J3.34(p34)
Comb3_data12: J3.35(p35)
Comb3_data13: J3.36(p36)
Comb3_data14: J3.37(p37)
Comb3_data15: J3.38(p38)
Comb4_data0: J3.3(p3)
Comb4_data1: J3.4(p4)
Comb4_data2: J3.5(p5)
Comb4_data3: J3.6(p6)
Comb4_data4: J3.7(p7)
Comb4_data5: J3.8(p8)
Comb4_data6: J3.9(p9)
Comb4_data7: J3.10(p10)
Comb4_data8: J3.11(p11)
Comb4_data9: J3.12(p12)
Comb4_data10: J3.13(p13)
Comb4_data11: J3.14(p14)
Comb4_data12: J3.15(p15)
Comb4_data13: J3.16(p16)
Comb4_data14: J3.17(p17)
Comb4_data15: J3.18(p18)
DemodA_data0: J5.3(p3)
DemodA_data1: J5.4(p4)
DemodA_data2: J5.5(p5)
DemodA_data3: J5.6(p6)
DemodA_data4: J5.7(p7)
DemodA_data5: J5.8(p8)
DemodA_data6: J5.9(p9)
DemodA_data7: J5.10(p10)
DemodA_data8: J5.11(p11)
DemodA_data9: J5.12(p12)
DemodA_data10: J5.13(p13)
DemodA_data11: J5.14(p14)
DemodA_data12: J5.15(p15)
DemodA_data13: J5.16(p16)
DemodA_data14: J5.17(p17)
DemodB_data0: J3.50(p50)
DemodB_data1: J3.51(p51)
DemodB_data2: J3.52(p52)
DemodB_data3: J3.53(p53)
DemodB_data4: J3.54(p54)
DemodB_data5: J3.55(p55)
DemodB_data6: J3.56(p56)
DemodB_data7: J3.57(p57)
DemodB_data8: J3.58(p58)
DemodB_data9: J3.59(p59)
DemodB_data10: J3.60(p60)
DemodB_data11: J3.61(p61)
DemodB_data12: J3.62(p62)
DemodB_data13: J3.63(p63)
DemodB_data14: J3.64(p64)
POWER_DATA0: UT32.2(B0)
POWER_DATA1: UT32.3(B1)
POWER_DATA2: UT32.5(B2)
POWER_DATA3: UT32.6(B3)
POWER_DATA4: UT32.8(B4)
NetJ3_21: J3.21(p21) UT75.16(R1)
NetJ3_22: J3.22(p22) UT75.15(R2)
NetJ3_39: J3.39(p39) UT75.14(R3)
NetJ3_40: J3.40(p40) UT75.13(R4)
NetJ3_47: J3.47(p47) UT75.10(R7)
NetJ3_48: J3.48(p48) UT75.9(R8)
NetJ4_1: J4.1(p1) ; sheet dac_block4/Comb_out_p
NetJ4_2: J4.2(p2) ; sheet dac_block3/Comb_out_p
NetJ4_3: J4.3(p3) ; sheet adc_block1/DemodB_in_p, sheet power_block1/DemodB_in_dc_p
NetJ4_6: J4.6(p6) ; sheet adc_block1/DemodA_in_p, sheet power_block1/DemodA_in_dc_p
NetJ4_7: J4.7(p7) ; sheet dac_block2/Comb_out_p
NetJ4_8: J4.8(p8) ; sheet dac_block1/Comb_out_p
NetJ4_9: J4.9(p9) ; sheet dac_block4/Comb_out_n
NetJ4_10: J4.10(p10) ; sheet dac_block3/Comb_out_n
NetJ4_11: J4.11(p11) ; sheet adc_block1/DemodB_in_n, sheet power_block1/DemodB_in_dc_n
NetJ4_12: J4.12(p12) RG1.2
NetJ4_13: J4.13(p13) ; sheet adc_block1/DemodA_in_n, sheet power_block1/DemodA_in_dc_n
NetJ4_14: J4.14(p14) ; sheet dac_block2/Comb_out_n
NetJ4_15: J4.15(p15) ; sheet dac_block1/Comb_out_n
NetJ5_19: J5.19(p19) UT74.16(R1)
NetJ5_20: J5.20(p20) UT74.15(R2)
NetJ5_21: J5.21(p21) J5.22(p22)
NetJ5_24: J5.24(p24) UT74.13(R4)
NetJ5_27: J5.27(p27) UT74.12(R5)
NetJ5_28: J5.28(p28) UT74.11(R6)
NetJ5_47: J5.47(p47) UT74.10(R7)
NetJ5_48: J5.48(p48) UT74.9(R8)
NetJ5_67: J5.67(p67) UT73.16(R1)
NetJ5_68: J5.68(p68) UT73.15(R2)
NetJ5_69: J5.69(p69) UT73.14(R3)
NetJ5_70: J5.70(p70) UT73.13(R4)
NetJ5_71: J5.71(p71) UT73.12(R5)
NetJ5_72: J5.72(p72) UT73.11(R6)
NetJ5_74: J5.74(p74) ; sheet power_block1/POWER_ENABLE
NetJ5_77: J5.77(p77) J5.78(p78) ; sheet power_block1/V6pRAW
NetJ5_79: J5.79(p79) J5.80(p80) J5.81(p81) J5.82(p82) ; sheet power_block1/V4RAW
NetJ5_83: J5.83(p83) J5.84(p84) ; sheet power_block1/V6nRAW
NetUT31_2: UT31.2(B0) ; sheet dac_block4/Comb_S0
NetUT31_3: UT31.3(B1) ; sheet dac_block4/Comb_S1
NetUT31_5: UT31.5(B2) ; sheet dac_block3/Comb_S0
NetUT31_6: UT31.6(B3) ; sheet dac_block3/Comb_S1
NetUT31_8: UT31.8(B4) ; sheet dac_block4/clock, sheet dac_block3/clock
NetUT31_9: UT31.9(B5) ; sheet adc_block1/clock
NetUT31_11: UT31.11(B6) ; sheet adc_block1/DemodB_S0
NetUT31_12: UT31.12(B7) ; sheet adc_block1/DemodB_S1
NetUT31_13: UT31.13(B8) ; sheet adc_block1/DemodA_S0
NetUT31_14: UT31.14(B9) ; sheet adc_block1/DemodA_S1
NetUT31_17: UT31.17(B11) ; sheet dac_block1/clock, sheet dac_block2/clock
NetUT31_19: UT31.19(B12) ; sheet dac_block2/Comb_S0
NetUT31_20: UT31.20(B13) ; sheet dac_block2/Comb_S1
NetUT31_22: UT31.22(B14) ; sheet dac_block1/Comb_S0
NetUT31_23: UT31.23(B15) ; sheet dac_block1/Comb_S1
NetUT31_26: UT31.26(A15) UT74.8(R8)
NetUT31_27: UT31.27(A14) UT74.7(R7)
NetUT31_29: UT31.29(A13) UT74.6(R6)
NetUT31_30: UT31.30(A12) UT74.5(R5)
NetUT31_32: UT31.32(A11) UT74.4(R4)
NetUT31_33: UT31.33(A10) UT74.3(R3)
NetUT31_35: UT31.35(A9) UT74.2(R2)
NetUT31_36: UT31.36(A8) UT74.1(R1)
NetUT31_37: UT31.37(A7) UT75.8(R8)
NetUT31_38: UT31.38(A6) UT75.7(R7)
NetUT31_40: UT31.40(A5) UT75.6(R6)
NetUT31_41: UT31.41(A4) UT75.5(R5)
NetUT31_43: UT31.43(A3) UT75.4(R4)
NetUT31_44: UT31.44(A2) UT75.3(R3)
NetUT31_46: UT31.46(A1) UT75.2(R2)
NetUT31_47: UT31.47(A0) UT75.1(R1)
NetUT32_13: UT32.13(B8) ; sheet power_block1/POWER_DATA_OUT
NetUT32_36: UT32.36(A8) UT73.6(R6)
NetUT32_41: UT32.41(A4) UT73.5(R5)
NetUT32_43: UT32.43(A3) UT73.4(R4)
NetUT32_44: UT32.44(A2) UT73.3(R3)
NetUT32_46: UT32.46(A1) UT73.2(R2)
NetUT32_47: UT32.47(A0) UT73.1(R1)
(unnamed): sheet dac_block1/VREF_IN, sheet adc_block1/VREFB_IN, sheet dac_block2/VREF_OUT
(unnamed): sheet dac_block4/VREF_IN, sheet adc_block1/VREFA_IN, sheet dac_block3/VREF_OUT  [a separate net that carries the same name]

Not connected (* = marked no-connect by the designer): J3 41(p41) 42(p42) 49(p49); J4 4(p4) 5(p5); J5 18(p18) 23(p23) 73(p73); J6 12 13 14 15 16 17 18; MH1 1(A); MH2 1(A); MH3 1(A); MH4 1(A); MH5 1(A); MH6 1(A); UT31 16(B10); UT32 4(EGND) 9(B5) 11(B6) 12(B7) 26(A15) 27(A14) 29(A13) 30(A12) 32(A11) 33(A10) 35(A9); UT73 7(R7) 8(R8) 9(R8) 10(R7)

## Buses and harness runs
bus Comb1_data[0..15] = sheet transceiver_block1/A[0..15]
bus Comb2_data[0..15] = sheet transceiver_block2/A[0..15]
bus Comb3_data[0..15] = sheet transceiver_block3/A[0..15]
bus Comb4_data[0..15] = sheet transceiver_block4/A[0..15]
bus DemodA_data[0..14] = sheet transceiver_block6/A[0..15]
bus DemodB_data[0..14] = sheet transceiver_block5/A[0..15]
bus POWER_DATA[0..4] = sheet power_block1/PWR_DATA[0..4]
bus RecA_DATA[0..15] = sheet adc_block1/DemodA_data[0..15] = sheet transceiver_block6/B[0..15]
bus RecB_DATA[0..15] = sheet adc_block1/DemodB_data[0..15] = sheet transceiver_block5/B[0..15]
bus Tran1_DATA[0..15] = sheet dac_block1/Comb_data[0..15] = sheet transceiver_block1/B[0..15]
bus Tran2_DATA[0..15] = sheet dac_block2/Comb_data[0..15] = sheet transceiver_block2/B[0..15]
bus Tran3_DATA[0..15] = sheet dac_block3/Comb_data[0..15] = sheet transceiver_block3/B[0..15]
bus Tran4_DATA[0..15] = sheet dac_block4/Comb_data[0..15] = sheet transceiver_block4/B[0..15]

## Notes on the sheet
- Layer Stackup Suggestion
- Silkscreen, Solder Mask
- 1. Top signal Traces
- 2. Ground (closes the RF shield)
- 3. +3V Analog plane, inner Signals for gain select, etc.
- 4. Power planes: VDD_EXT, +3VDigital, +5V analog
- 5. signal traces for clock and some voltage references. -5V power plane
- 6. Bottom signal traces
- All traces should be 100 +-10 ohm controlledimpedance. Differential pairs should be runtogether.
- Try to make the layout compatible with the www.pcbexpress.com specifications:
- Allowed Drill sizes: 0.008 .0135  .020  .025  .029  .035  .040 .046  .052  .061  .067  .079  .093  .11  .125  .15  .192
- Mount Holes: 4-40, back of board are connected to external ground, front of board are floating.
- All spaces/traces are a minimum of .007 (7 mil) or larger.
- RF Shield (build this partcarefully!). All mounting pointsare connected to ANALOG ground.
- RF Shield outer dimensions are 80x73mm.
- Module B
- DB15f Pinout
- B Nuller+-    1,9
- B Carrier+-   2,10
- B Demod+-     3,11
- Ground        12
- N/C           4,5
- A Carrier+-   7,14
- A Demod+-     6,13
- A Nuller+-    8,15
- Connect DB15 shell to analog ground.
- This connection pf p21 to p22 is for Rev3 only. The FPGA will toggle p21 high then low, and if it sees this signal on p22, it will know it is talking to a Rev 3 board.
- Module A
- 4V
- 6V
- 6Vneg

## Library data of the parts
CT25 = CAPACITOR POL: COMPFIXED: NO; COMPGROUP: 0; COMPHEIGHT: 0.000; COMPLOC: [969.633,2534.367]; COMPROT: 270; COMPSIDE: TOP
CT26 = C: PSpiceTemplate: C^@REFDES %1 %2 ?TOLERANCE|C^@REFDES| @VALUE ?IC/IC=@IC/ ?TOLERANCE|\n.model C^@REFDES CAP C=1 DEV=@TOLERANCE%|; COMPFIXED: NO; COMPGROUP: 0; COMPHEIGHT: 0.000; COMPLOC: [934.633,2329.367]; COMPSIDE: TOP
CT27 = CAPACITOR POL: COMPFIXED: NO; COMPGROUP: 0; COMPHEIGHT: 0.000; COMPLOC: [1189.633,2524.367]; COMPROT: 270; COMPSIDE: TOP
CT28 = C: PSpiceTemplate: C^@REFDES %1 %2 ?TOLERANCE|C^@REFDES| @VALUE ?IC/IC=@IC/ ?TOLERANCE|\n.model C^@REFDES CAP C=1 DEV=@TOLERANCE%|; COMPFIXED: NO; COMPGROUP: 0; COMPHEIGHT: 0.000; COMPLOC: [1174.633,2279.367]; COMPROT: 90; COMPSIDE: TOP
CT29 = CAPACITOR POL: COMPFIXED: NO; COMPGROUP: 0; COMPHEIGHT: 0.000; COMPLOC: [969.633,484.367]; COMPROT: 270; COMPSIDE: TOP
CT30 = C: PSpiceTemplate: C^@REFDES %1 %2 ?TOLERANCE|C^@REFDES| @VALUE ?IC/IC=@IC/ ?TOLERANCE|\n.model C^@REFDES CAP C=1 DEV=@TOLERANCE%|; COMPFIXED: NO; COMPGROUP: 0; COMPHEIGHT: 0.000; COMPLOC: [939.633,284.367]; COMPSIDE: TOP
CT31 = CAPACITOR POL: COMPFIXED: NO; COMPGROUP: 0; COMPHEIGHT: 0.000; COMPLOC: [1189.633,469.367]; COMPROT: 270; COMPSIDE: TOP
CT32 = C: PSpiceTemplate: C^@REFDES %1 %2 ?TOLERANCE|C^@REFDES| @VALUE ?IC/IC=@IC/ ?TOLERANCE|\n.model C^@REFDES CAP C=1 DEV=@TOLERANCE%|; COMPFIXED: NO; COMPGROUP: 0; COMPHEIGHT: 0.000; COMPLOC: [1174.633,228.367]; COMPROT: 90; COMPSIDE: TOP
J3 = IEEE1386 Amp120527-1 Plug 64pin: COMPFIXED: NO; COMPGROUP: 0; COMPHEIGHT: 0.000; COMPLOC: [194.633,3349.433]; COMPROT: 90; COMPSIDE: TOP
J4 = DB15_FEMALE: COMPFIXED: NO; COMPGROUP: 0; COMPHEIGHT: 0.000; COMPLOC: [4502.733,1338.467]; COMPROT: 270; COMPSIDE: TOP
J5 = IEEE1386 Amp120527-2 Plug84pin: COMPFIXED: NO; COMPGROUP: 0; COMPHEIGHT: 0.000; COMPLOC: [194.633,1904.367]; COMPROT: 90; COMPSIDE: TOP
J6 = CONN FLEX 23: COMPROT: 270; COMPLOC: [4237.633,3305.000]; COMPFIXED: NO; COMPGROUP: 0; COMPHEIGHT: 0.000; COMPSIDE: TOP
MH1 = SOUNDER_0: COMPFIXED: NO; COMPGROUP: 0; COMPHEIGHT: 0.000; COMPLOC: [254.633,3525.000]; COMPSIDE: TOP
MH2 = SOUNDER_0: COMPFIXED: NO; COMPGROUP: 0; COMPHEIGHT: 0.000; COMPLOC: [254.633,100.000]; COMPSIDE: TOP
MH3 = SOUNDER_0: COMPFIXED: NO; COMPGROUP: 0; COMPHEIGHT: 0.000; COMPLOC: [4254.633,100.000]; COMPSIDE: TOP
MH4 = SOUNDER_0: COMPFIXED: NO; COMPGROUP: 0; COMPHEIGHT: 0.000; COMPLOC: [4254.633,3525.000]; COMPSIDE: TOP
MH5 = SOUNDER_0: COMPFIXED: NO; COMPGROUP: 0; COMPHEIGHT: 0.000; COMPLOC: [2579.633,3525.000]; COMPSIDE: TOP
MH6 = SOUNDER_0: COMPFIXED: NO; COMPGROUP: 0; COMPHEIGHT: 0.000; COMPLOC: [3179.633,100.000]; COMPSIDE: TOP
RG1 = R
UT31 = 74LVT16245 Transceiver_0: COMPFIXED: NO; COMPGROUP: 0; COMPHEIGHT: 0.000; COMPLOC: [1188.633,2599.367]; COMPROT: 90; COMPSIDE: BOT; FPLIST: TSSOP48_.4MMPITCH,TSSOP48_.4MMPITCH_NARROW
UT32 = 74LVT16245 Transceiver_0: COMPFIXED: NO; COMPGROUP: 0; COMPHEIGHT: 0.000; COMPLOC: [1189.633,549.367]; COMPROT: 90; COMPSIDE: BOT; FPLIST: TSSOP48_.4MMPITCH,TSSOP48_.4MMPITCH_NARROW
UT73 = R-PACK_1: COMPFIXED: NO; COMPGROUP: 0; COMPHEIGHT: 0.000; COMPLOC: [783.633,464.367]; COMPROT: 90; COMPSIDE: BOT
UT74 = R-PACK_1: COMPFIXED: NO; COMPGROUP: 0; COMPHEIGHT: 0.000; COMPLOC: [779.633,2322.367]; COMPROT: 90; COMPSIDE: BOT
UT75 = R-PACK_1: COMPFIXED: NO; COMPGROUP: 0; COMPHEIGHT: 0.000; COMPLOC: [779.633,2514.367]; COMPROT: 90; COMPSIDE: BOT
